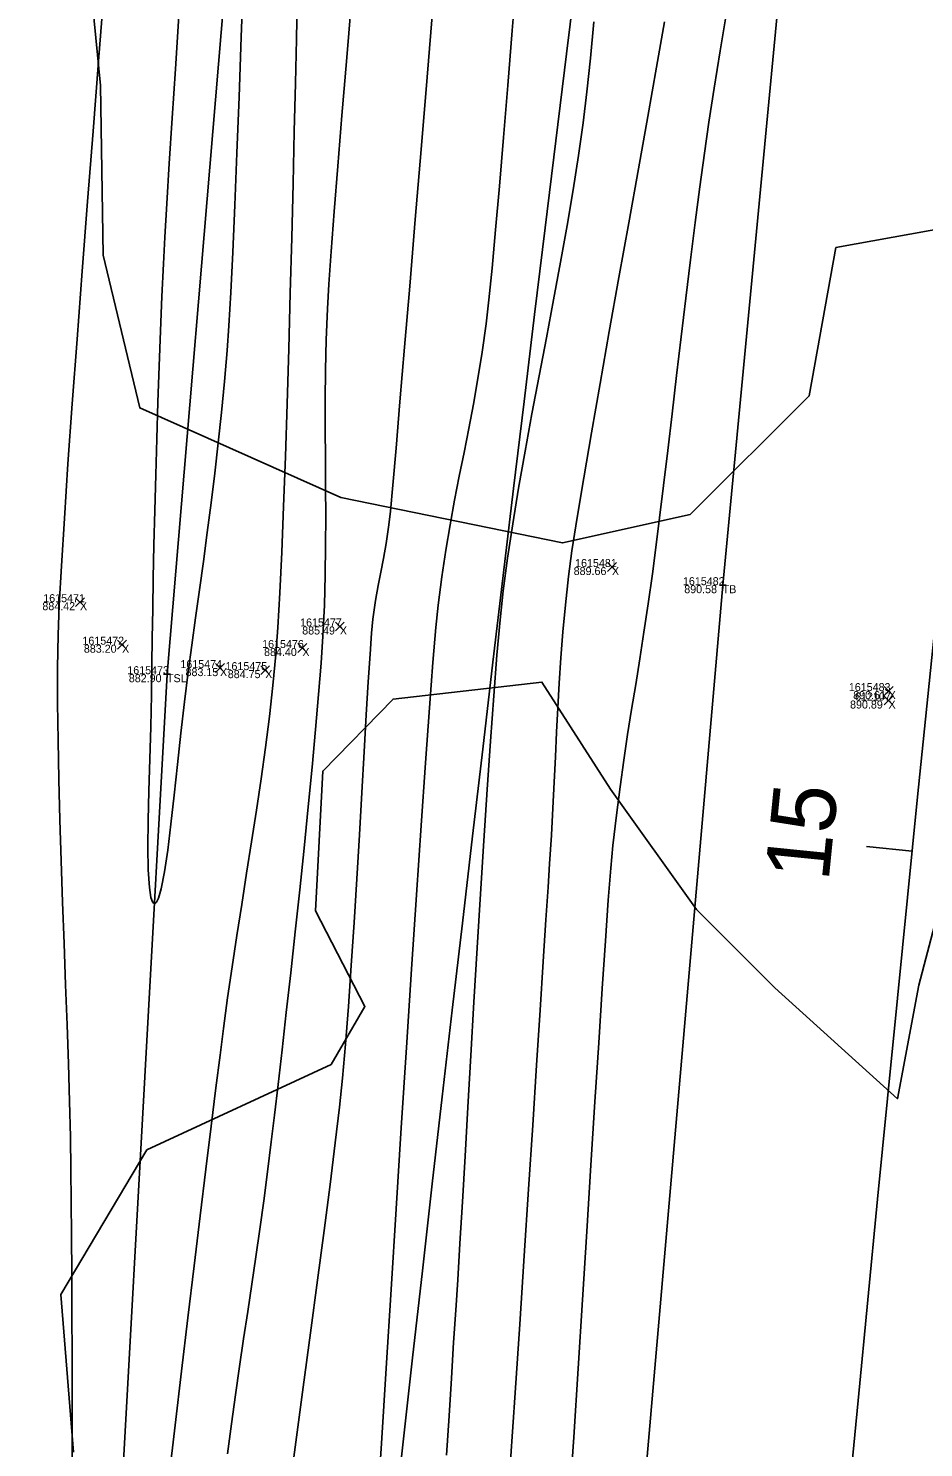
# Model space of a CAD drawing. Extents: x 1957117 to 1971063, y 701601 to 715861.
# Drawn here: x 1962727.3 to 1962766.5, y 703470.4 to 703532.5 of the extents above; entities that cross this region are included whole.
import ezdxf

# ---------------------------------------------------------------- set-up
doc = ezdxf.new("R2010")
doc.units = 0
for name, color, linetype in [('AP_X_Lights', 7, 'Continuous'), ('DT_X_Break_Line', 7, 'Continuous'), ('DT_X_Contour_Major', 7, 'Continuous'), ('DT_X_Contour_Minor', 7, 'Continuous'), ('GE_X_CL_20', 7, 'Continuous'), ('PV_P_Drive', 7, 'Continuous'), ('PV_P_Shoulder', 7, 'Continuous'), ('RS_Raster1', 7, 'Continuous'), ('RW_X_Esmt_RR', 7, 'Continuous'), ('SC_Scratch1', 7, 'Continuous'), ('VG_X_Tree_Line_Rt', 7, 'Continuous')]:
    doc.layers.add(name, color=color, linetype=linetype)

msp = doc.modelspace()

# ---------------------------------------------------------------- linework, layer by layer
at = {"layer": 'AP_X_Lights'}
for p, q in [((1962752.654, 703508.755), (1962753.042, 703509.145)), ((1962752.654, 703509.145), (1962753.042, 703508.755)), ((1962729.394, 703507.219), (1962729.782, 703507.609)), ((1962729.394, 703507.609), (1962729.782, 703507.219)), ((1962740.757, 703506.156), (1962741.145, 703506.546)), ((1962740.757, 703506.546), (1962741.145, 703506.156)), ((1962731.236, 703505.359), (1962731.624, 703505.749)), ((1962731.236, 703505.749), (1962731.624, 703505.359)), ((1962739.119, 703505.214), (1962739.507, 703505.604)), ((1962739.119, 703505.604), (1962739.507, 703505.214)), ((1962735.518, 703504.336), (1962735.906, 703504.726)), ((1962735.518, 703504.726), (1962735.906, 703504.336)), ((1962737.495, 703504.247), (1962737.883, 703504.637)), ((1962737.495, 703504.637), (1962737.883, 703504.247)), ((1962764.747, 703502.918), (1962765.135, 703503.308)), ((1962764.747, 703503.308), (1962765.135, 703502.918)), ((1962764.754, 703503.33), (1962765.142, 703503.72)), ((1962764.754, 703503.72), (1962765.142, 703503.33))]:
    msp.add_line(p, q, dxfattribs=at)
at = {"layer": 'DT_X_Break_Line'}
for points in [[(1962730.818, 703457.798), (1962733.395, 703504.264), (1962741.916, 703605.02), (1962747.624, 703652.087), (1962756.592, 703704.666), (1962761.935, 703754.654), (1962770.271, 703804.276), (1962778.004, 703852.465), (1962787.236, 703902.544), (1962794.92, 703952.201), (1962805.163, 704000.74), (1962815.72, 704050.002), (1962825.218, 704099.5), (1962834.811, 704148.707), (1962846.035, 704198.31), (1962854.549, 704243.654), (1962868.069, 704295.231)], [(1962892.064, 704289.931), (1962881.011, 704234.451), (1962871.969, 704195.37), (1962858.193, 704145.387), (1962849.618, 704095.769), (1962840.196, 704046.83), (1962828.044, 703997.69), (1962822.426, 703949.671), (1962812.618, 703898.591), (1962803.468, 703849.395), (1962793.965, 703803.71), (1962788.733, 703751.727), (1962780.252, 703700.82), (1962774.948, 703651.755), (1962769.57, 703604.236), (1962761.597, 703549.082), (1962757.692, 703508.157), (1962753.044, 703454.513)]]:
    msp.add_lwpolyline(points, dxfattribs=at)
at = {"layer": 'DT_X_Contour_Major'}
for points in [[(1962741.449, 703533.54), (1962741.238, 703531.059), (1962741.04, 703528.692), (1962740.86, 703526.487), (1962740.702, 703524.493), (1962740.571, 703522.755), (1962740.472, 703521.322), (1962740.408, 703520.242), (1962740.354, 703518.887), (1962740.324, 703517.563), (1962740.312, 703516.265), (1962740.312, 703514.985), (1962740.32, 703513.715), (1962740.33, 703512.449), (1962740.336, 703511.179), (1962740.332, 703509.899), (1962740.314, 703508.602), (1962740.275, 703507.279), (1962740.211, 703505.925), (1962740.133, 703504.743), (1962740.025, 703503.374), (1962739.893, 703501.85), (1962739.74, 703500.202), (1962739.571, 703498.461), (1962739.388, 703496.659), (1962739.197, 703494.828), (1962739.001, 703492.999), (1962738.805, 703491.202), (1962738.612, 703489.471), (1962738.426, 703487.835), (1962738.252, 703486.328), (1962738.094, 703484.979), (1962737.955, 703483.82), (1962737.791, 703482.506), (1962737.623, 703481.236), (1962737.451, 703480), (1962737.276, 703478.788), (1962737.1, 703477.592), (1962736.923, 703476.4), (1962736.745, 703475.204), (1962736.567, 703473.993), (1962736.391, 703472.758), (1962736.216, 703471.488), (1962736.043, 703470.174)], [(1962741.449, 703533.54), (1962741.238, 703531.059), (1962741.04, 703528.692), (1962740.86, 703526.487), (1962740.702, 703524.493), (1962740.571, 703522.755), (1962740.472, 703521.322), (1962740.408, 703520.242), (1962740.354, 703518.887), (1962740.324, 703517.563), (1962740.312, 703516.265), (1962740.312, 703514.985), (1962740.32, 703513.715), (1962740.33, 703512.449), (1962740.336, 703511.179), (1962740.332, 703509.899), (1962740.314, 703508.602), (1962740.275, 703507.279), (1962740.211, 703505.925), (1962740.133, 703504.743), (1962740.025, 703503.374), (1962739.893, 703501.85), (1962739.74, 703500.202), (1962739.571, 703498.461), (1962739.388, 703496.659), (1962739.197, 703494.828), (1962739.001, 703492.999), (1962738.805, 703491.202), (1962738.612, 703489.471), (1962738.426, 703487.835), (1962738.252, 703486.328), (1962738.094, 703484.979), (1962737.955, 703483.82), (1962737.791, 703482.506), (1962737.623, 703481.236), (1962737.451, 703480), (1962737.276, 703478.788), (1962737.1, 703477.592), (1962736.923, 703476.4), (1962736.745, 703475.204), (1962736.567, 703473.993), (1962736.391, 703472.758), (1962736.216, 703471.488), (1962736.043, 703470.174)], [(1962757.877, 703533.28), (1962757.583, 703531.531), (1962757.318, 703529.891), (1962757.09, 703528.406), (1962756.896, 703527.055), (1962756.698, 703525.584), (1962756.495, 703524.02), (1962756.29, 703522.387), (1962756.084, 703520.709), (1962755.88, 703519.012), (1962755.678, 703517.32), (1962755.481, 703515.657), (1962755.289, 703514.05), (1962755.106, 703512.521), (1962754.932, 703511.097), (1962754.769, 703509.802), (1962754.62, 703508.66), (1962754.434, 703507.339), (1962754.25, 703506.107), (1962754.067, 703504.942), (1962753.887, 703503.821), (1962753.71, 703502.723), (1962753.536, 703501.624), (1962753.367, 703500.502), (1962753.203, 703499.335), (1962753.044, 703498.101), (1962752.892, 703496.776), (1962752.8, 703495.787), (1962752.69, 703494.382), (1962752.564, 703492.608), (1962752.424, 703490.515), (1962752.271, 703488.148), (1962752.107, 703485.557), (1962751.933, 703482.788), (1962751.752, 703479.891), (1962751.564, 703476.911), (1962751.372, 703473.899), (1962751.178, 703470.9), (1962750.982, 703467.964)], [(1962757.877, 703533.28), (1962757.583, 703531.531), (1962757.318, 703529.891), (1962757.09, 703528.406), (1962756.896, 703527.055), (1962756.698, 703525.584), (1962756.495, 703524.02), (1962756.29, 703522.387), (1962756.084, 703520.709), (1962755.88, 703519.012), (1962755.678, 703517.32), (1962755.481, 703515.657), (1962755.289, 703514.05), (1962755.106, 703512.521), (1962754.932, 703511.097), (1962754.769, 703509.802), (1962754.62, 703508.66), (1962754.434, 703507.339), (1962754.25, 703506.107), (1962754.067, 703504.942), (1962753.887, 703503.821), (1962753.71, 703502.723), (1962753.536, 703501.624), (1962753.367, 703500.502), (1962753.203, 703499.335), (1962753.044, 703498.101), (1962752.892, 703496.776), (1962752.8, 703495.787), (1962752.69, 703494.382), (1962752.564, 703492.608), (1962752.424, 703490.515), (1962752.271, 703488.148), (1962752.107, 703485.557), (1962751.933, 703482.788), (1962751.752, 703479.891), (1962751.564, 703476.911), (1962751.372, 703473.899), (1962751.178, 703470.9), (1962750.982, 703467.964)]]:
    msp.add_lwpolyline(points, dxfattribs=at)
at = {"layer": 'DT_X_Contour_Minor'}
for points in [[(1962736.74, 703534.821), (1962736.641, 703532.124), (1962736.544, 703529.52), (1962736.449, 703527.054), (1962736.358, 703524.773), (1962736.27, 703522.723), (1962736.185, 703520.95), (1962736.105, 703519.5), (1962736.03, 703518.418), (1962735.911, 703517.061), (1962735.778, 703515.713), (1962735.633, 703514.378), (1962735.48, 703513.057), (1962735.319, 703511.753), (1962735.153, 703510.466), (1962734.984, 703509.199), (1962734.815, 703507.955), (1962734.648, 703506.734), (1962734.484, 703505.539), (1962734.325, 703504.371), (1962734.16, 703503.059), (1962734.004, 703501.691), (1962733.854, 703500.313), (1962733.709, 703498.97), (1962733.567, 703497.709), (1962733.427, 703496.576), (1962733.285, 703495.617), (1962733.142, 703494.877), (1962733.024, 703494.476), (1962732.933, 703494.3), (1962732.871, 703494.249), (1962732.839, 703494.244), (1962732.809, 703494.253), (1962732.754, 703494.314), (1962732.687, 703494.505), (1962732.623, 703494.931), (1962732.578, 703495.703), (1962732.564, 703496.697), (1962732.576, 703497.867), (1962732.604, 703499.165), (1962732.642, 703500.544), (1962732.682, 703501.957), (1962732.717, 703503.356), (1962732.738, 703504.695), (1962732.751, 703505.839), (1962732.77, 703507.103), (1962732.795, 703508.467), (1962732.825, 703509.914), (1962732.861, 703511.425), (1962732.902, 703512.981), (1962732.947, 703514.564), (1962732.997, 703516.154), (1962733.052, 703517.733), (1962733.111, 703519.282), (1962733.174, 703520.783), (1962733.24, 703522.216), (1962733.302, 703523.373), (1962733.387, 703524.846), (1962733.495, 703526.595), (1962733.62, 703528.575), (1962733.762, 703530.743), (1962733.915, 703533.057)], [(1962736.74, 703534.821), (1962736.641, 703532.124), (1962736.544, 703529.52), (1962736.449, 703527.054), (1962736.358, 703524.773), (1962736.27, 703522.723), (1962736.185, 703520.95), (1962736.105, 703519.5), (1962736.03, 703518.418), (1962735.911, 703517.061), (1962735.778, 703515.713), (1962735.633, 703514.378), (1962735.48, 703513.057), (1962735.319, 703511.753), (1962735.153, 703510.466), (1962734.984, 703509.199), (1962734.815, 703507.955), (1962734.648, 703506.734), (1962734.484, 703505.539), (1962734.325, 703504.371), (1962734.16, 703503.059), (1962734.004, 703501.691), (1962733.854, 703500.313), (1962733.709, 703498.97), (1962733.567, 703497.709), (1962733.427, 703496.576), (1962733.285, 703495.617), (1962733.142, 703494.877), (1962733.024, 703494.476), (1962732.933, 703494.3), (1962732.871, 703494.249), (1962732.839, 703494.244), (1962732.809, 703494.253), (1962732.754, 703494.314), (1962732.687, 703494.505), (1962732.623, 703494.931), (1962732.578, 703495.703), (1962732.564, 703496.697), (1962732.576, 703497.867), (1962732.604, 703499.165), (1962732.642, 703500.544), (1962732.682, 703501.957), (1962732.717, 703503.356), (1962732.738, 703504.695), (1962732.751, 703505.839), (1962732.77, 703507.103), (1962732.795, 703508.467), (1962732.825, 703509.914), (1962732.861, 703511.425), (1962732.902, 703512.981), (1962732.947, 703514.564), (1962732.997, 703516.154), (1962733.052, 703517.733), (1962733.111, 703519.282), (1962733.174, 703520.783), (1962733.24, 703522.216), (1962733.302, 703523.373), (1962733.387, 703524.846), (1962733.495, 703526.595), (1962733.62, 703528.575), (1962733.762, 703530.743), (1962733.915, 703533.057)], [(1962748.692, 703534.882), (1962748.493, 703532.409), (1962748.299, 703530.011), (1962748.111, 703527.732), (1962747.931, 703525.613), (1962747.763, 703523.696), (1962747.607, 703522.025), (1962747.468, 703520.641), (1962747.346, 703519.587), (1962747.175, 703518.354), (1962746.99, 703517.19), (1962746.794, 703516.08), (1962746.591, 703515.008), (1962746.384, 703513.96), (1962746.176, 703512.919), (1962745.971, 703511.87), (1962745.772, 703510.798), (1962745.583, 703509.688), (1962745.406, 703508.523), (1962745.247, 703507.289), (1962745.148, 703506.302), (1962745.022, 703504.782), (1962744.871, 703502.791), (1962744.698, 703500.392), (1962744.507, 703497.645), (1962744.303, 703494.614), (1962744.087, 703491.36), (1962743.865, 703487.945), (1962743.638, 703484.431), (1962743.412, 703480.88), (1962743.189, 703477.353), (1962742.973, 703473.913), (1962742.767, 703470.621), (1962742.576, 703467.54)], [(1962748.692, 703534.882), (1962748.493, 703532.409), (1962748.299, 703530.011), (1962748.111, 703527.732), (1962747.931, 703525.613), (1962747.763, 703523.696), (1962747.607, 703522.025), (1962747.468, 703520.641), (1962747.346, 703519.587), (1962747.175, 703518.354), (1962746.99, 703517.19), (1962746.794, 703516.08), (1962746.591, 703515.008), (1962746.384, 703513.96), (1962746.176, 703512.919), (1962745.971, 703511.87), (1962745.772, 703510.798), (1962745.583, 703509.688), (1962745.406, 703508.523), (1962745.247, 703507.289), (1962745.148, 703506.302), (1962745.022, 703504.782), (1962744.871, 703502.791), (1962744.698, 703500.392), (1962744.507, 703497.645), (1962744.303, 703494.614), (1962744.087, 703491.36), (1962743.865, 703487.945), (1962743.638, 703484.431), (1962743.412, 703480.88), (1962743.189, 703477.353), (1962742.973, 703473.913), (1962742.767, 703470.621), (1962742.576, 703467.54)], [(1962729.245, 703468.762), (1962729.247, 703470.683), (1962729.247, 703472.596), (1962729.243, 703474.478), (1962729.237, 703476.306), (1962729.229, 703478.055), (1962729.219, 703479.702), (1962729.208, 703481.223), (1962729.195, 703482.595), (1962729.172, 703484.036), (1962729.135, 703485.584), (1962729.085, 703487.22), (1962729.027, 703488.926), (1962728.963, 703490.686), (1962728.897, 703492.482), (1962728.831, 703494.295), (1962728.768, 703496.107), (1962728.712, 703497.902), (1962728.666, 703499.661), (1962728.632, 703501.367), (1962728.614, 703503.002), (1962728.614, 703504.548), (1962728.636, 703505.987), (1962728.686, 703507.287), (1962728.778, 703509.002), (1962728.906, 703511.078), (1962729.066, 703513.459), (1962729.253, 703516.09), (1962729.461, 703518.917), (1962729.685, 703521.883), (1962729.921, 703524.935), (1962730.162, 703528.016), (1962730.403, 703531.072), (1962730.64, 703534.047)], [(1962729.245, 703468.762), (1962729.247, 703470.683), (1962729.247, 703472.596), (1962729.243, 703474.478), (1962729.237, 703476.306), (1962729.229, 703478.055), (1962729.219, 703479.702), (1962729.208, 703481.223), (1962729.195, 703482.595), (1962729.172, 703484.036), (1962729.135, 703485.584), (1962729.085, 703487.22), (1962729.027, 703488.926), (1962728.963, 703490.686), (1962728.897, 703492.482), (1962728.831, 703494.295), (1962728.768, 703496.107), (1962728.712, 703497.902), (1962728.666, 703499.661), (1962728.632, 703501.367), (1962728.614, 703503.002), (1962728.614, 703504.548), (1962728.636, 703505.987), (1962728.686, 703507.287), (1962728.778, 703509.002), (1962728.906, 703511.078), (1962729.066, 703513.459), (1962729.253, 703516.09), (1962729.461, 703518.917), (1962729.685, 703521.883), (1962729.921, 703524.935), (1962730.162, 703528.016), (1962730.403, 703531.072), (1962730.64, 703534.047)], [(1962739.088, 703533.717), (1962739.051, 703532.035), (1962739.008, 703530.111), (1962738.959, 703527.99), (1962738.905, 703525.721), (1962738.846, 703523.35), (1962738.783, 703520.923), (1962738.715, 703518.488), (1962738.643, 703516.09), (1962738.569, 703513.778), (1962738.491, 703511.597), (1962738.41, 703509.595), (1962738.327, 703507.818), (1962738.243, 703506.313), (1962738.157, 703505.127), (1962738.028, 703503.775), (1962737.874, 703502.416), (1962737.7, 703501.052), (1962737.51, 703499.683), (1962737.307, 703498.312), (1962737.095, 703496.94), (1962736.878, 703495.568), (1962736.661, 703494.198), (1962736.447, 703492.832), (1962736.24, 703491.47), (1962736.045, 703490.114), (1962735.864, 703488.766), (1962735.717, 703487.608), (1962735.536, 703486.174), (1962735.327, 703484.501), (1962735.095, 703482.623), (1962734.843, 703480.577), (1962734.578, 703478.399), (1962734.303, 703476.125), (1962734.024, 703473.789), (1962733.746, 703471.43), (1962733.473, 703469.081)], [(1962739.088, 703533.717), (1962739.051, 703532.035), (1962739.008, 703530.111), (1962738.959, 703527.99), (1962738.905, 703525.721), (1962738.846, 703523.35), (1962738.783, 703520.923), (1962738.715, 703518.488), (1962738.643, 703516.09), (1962738.569, 703513.778), (1962738.491, 703511.597), (1962738.41, 703509.595), (1962738.327, 703507.818), (1962738.243, 703506.313), (1962738.157, 703505.127), (1962738.028, 703503.775), (1962737.874, 703502.416), (1962737.7, 703501.052), (1962737.51, 703499.683), (1962737.307, 703498.312), (1962737.095, 703496.94), (1962736.878, 703495.568), (1962736.661, 703494.198), (1962736.447, 703492.832), (1962736.24, 703491.47), (1962736.045, 703490.114), (1962735.864, 703488.766), (1962735.717, 703487.608), (1962735.536, 703486.174), (1962735.327, 703484.501), (1962735.095, 703482.623), (1962734.843, 703480.577), (1962734.578, 703478.399), (1962734.303, 703476.125), (1962734.024, 703473.789), (1962733.746, 703471.43), (1962733.473, 703469.081)], [(1962745.039, 703533.592), (1962744.772, 703530.38), (1962744.507, 703527.209), (1962744.252, 703524.142), (1962744.009, 703521.24), (1962743.784, 703518.565), (1962743.582, 703516.182), (1962743.408, 703514.15), (1962743.266, 703512.535), (1962743.162, 703511.396), (1962743.1, 703510.798), (1962742.981, 703509.98), (1962742.86, 703509.317), (1962742.74, 703508.733), (1962742.622, 703508.148), (1962742.506, 703507.485), (1962742.394, 703506.666), (1962742.338, 703506.063), (1962742.271, 703505.135), (1962742.195, 703503.929), (1962742.109, 703502.49), (1962742.015, 703500.864), (1962741.913, 703499.096), (1962741.805, 703497.233), (1962741.692, 703495.319), (1962741.573, 703493.402), (1962741.451, 703491.526), (1962741.325, 703489.737), (1962741.198, 703488.08), (1962741.069, 703486.603), (1962740.936, 703485.328), (1962740.753, 703483.764), (1962740.527, 703481.953), (1962740.266, 703479.937), (1962739.978, 703477.759), (1962739.671, 703475.461), (1962739.352, 703473.087), (1962739.029, 703470.678), (1962738.709, 703468.276)], [(1962745.039, 703533.592), (1962744.772, 703530.38), (1962744.507, 703527.209), (1962744.252, 703524.142), (1962744.009, 703521.24), (1962743.784, 703518.565), (1962743.582, 703516.182), (1962743.408, 703514.15), (1962743.266, 703512.535), (1962743.162, 703511.396), (1962743.1, 703510.798), (1962742.981, 703509.98), (1962742.86, 703509.317), (1962742.74, 703508.733), (1962742.622, 703508.148), (1962742.506, 703507.485), (1962742.394, 703506.666), (1962742.338, 703506.063), (1962742.271, 703505.135), (1962742.195, 703503.929), (1962742.109, 703502.49), (1962742.015, 703500.864), (1962741.913, 703499.096), (1962741.805, 703497.233), (1962741.692, 703495.319), (1962741.573, 703493.402), (1962741.451, 703491.526), (1962741.325, 703489.737), (1962741.198, 703488.08), (1962741.069, 703486.603), (1962740.936, 703485.328), (1962740.753, 703483.764), (1962740.527, 703481.953), (1962740.266, 703479.937), (1962739.978, 703477.759), (1962739.671, 703475.461), (1962739.352, 703473.087), (1962739.029, 703470.678), (1962738.709, 703468.276)], [(1962752.062, 703532.787), (1962751.911, 703531.209), (1962751.754, 703529.732), (1962751.592, 703528.376), (1962751.394, 703526.946), (1962751.158, 703525.444), (1962750.892, 703523.883), (1962750.603, 703522.277), (1962750.298, 703520.638), (1962749.983, 703518.979), (1962749.665, 703517.313), (1962749.353, 703515.654), (1962749.051, 703514.014), (1962748.768, 703512.407), (1962748.51, 703510.846), (1962748.285, 703509.343), (1962748.099, 703507.913), (1962747.963, 703506.636), (1962747.823, 703505.09), (1962747.68, 703503.313), (1962747.535, 703501.343), (1962747.389, 703499.218), (1962747.243, 703496.976), (1962747.098, 703494.655), (1962746.955, 703492.292), (1962746.816, 703489.926), (1962746.681, 703487.594), (1962746.551, 703485.335), (1962746.428, 703483.187), (1962746.312, 703481.187), (1962746.205, 703479.373), (1962746.107, 703477.784), (1962746.021, 703476.457), (1962745.926, 703475.034), (1962745.827, 703473.487), (1962745.725, 703471.84), (1962745.619, 703470.117)], [(1962752.062, 703532.787), (1962751.911, 703531.209), (1962751.754, 703529.732), (1962751.592, 703528.376), (1962751.394, 703526.946), (1962751.158, 703525.444), (1962750.892, 703523.883), (1962750.603, 703522.277), (1962750.298, 703520.638), (1962749.983, 703518.979), (1962749.665, 703517.313), (1962749.353, 703515.654), (1962749.051, 703514.014), (1962748.768, 703512.407), (1962748.51, 703510.846), (1962748.285, 703509.343), (1962748.099, 703507.913), (1962747.963, 703506.636), (1962747.823, 703505.09), (1962747.68, 703503.313), (1962747.535, 703501.343), (1962747.389, 703499.218), (1962747.243, 703496.976), (1962747.098, 703494.655), (1962746.955, 703492.292), (1962746.816, 703489.926), (1962746.681, 703487.594), (1962746.551, 703485.335), (1962746.428, 703483.187), (1962746.312, 703481.187), (1962746.205, 703479.373), (1962746.107, 703477.784), (1962746.021, 703476.457), (1962745.926, 703475.034), (1962745.827, 703473.487), (1962745.725, 703471.84), (1962745.619, 703470.117)], [(1962755.148, 703532.789), (1962754.804, 703530.806), (1962754.422, 703528.646), (1962754.012, 703526.359), (1962753.587, 703523.998), (1962753.157, 703521.612), (1962752.734, 703519.254), (1962752.328, 703516.974), (1962751.951, 703514.823), (1962751.613, 703512.853), (1962751.327, 703511.114), (1962751.102, 703509.658), (1962750.951, 703508.536), (1962750.814, 703507.292), (1962750.703, 703506.11), (1962750.612, 703504.977), (1962750.539, 703503.879), (1962750.477, 703502.8), (1962750.424, 703501.728), (1962750.374, 703500.649), (1962750.323, 703499.547), (1962750.267, 703498.41), (1962750.201, 703497.223), (1962750.121, 703495.972), (1962750.054, 703494.957), (1962749.961, 703493.519), (1962749.845, 703491.708), (1962749.709, 703489.576), (1962749.555, 703487.171), (1962749.387, 703484.546), (1962749.206, 703481.749), (1962749.015, 703478.833), (1962748.818, 703475.847), (1962748.615, 703472.842), (1962748.411, 703469.868)], [(1962755.148, 703532.789), (1962754.804, 703530.806), (1962754.422, 703528.646), (1962754.012, 703526.359), (1962753.587, 703523.998), (1962753.157, 703521.612), (1962752.734, 703519.254), (1962752.328, 703516.974), (1962751.951, 703514.823), (1962751.613, 703512.853), (1962751.327, 703511.114), (1962751.102, 703509.658), (1962750.951, 703508.536), (1962750.814, 703507.292), (1962750.703, 703506.11), (1962750.612, 703504.977), (1962750.539, 703503.879), (1962750.477, 703502.8), (1962750.424, 703501.728), (1962750.374, 703500.649), (1962750.323, 703499.547), (1962750.267, 703498.41), (1962750.201, 703497.223), (1962750.121, 703495.972), (1962750.054, 703494.957), (1962749.961, 703493.519), (1962749.845, 703491.708), (1962749.709, 703489.576), (1962749.555, 703487.171), (1962749.387, 703484.546), (1962749.206, 703481.749), (1962749.015, 703478.833), (1962748.818, 703475.847), (1962748.615, 703472.842), (1962748.411, 703469.868)]]:
    msp.add_lwpolyline(points, dxfattribs=at)
at = {"layer": 'GE_X_CL_20'}
msp.add_line((1962765.974, 703496.53), (1962763.984, 703496.73), dxfattribs=at)
msp.add_arc((1968466.781, 702923.066), 5729.578, 166.495347, 177.813939, dxfattribs=at)
at = {"layer": 'PV_P_Drive'}
for p, q in [((1962757.692, 703508.303), (1962757.692, 703508.011)), ((1962757.546, 703508.157), (1962757.838, 703508.157)), ((1962757.692, 703508.157), (1962757.692, 703508.157)), ((1962733.249, 703504.264), (1962733.541, 703504.264)), ((1962733.395, 703504.41), (1962733.395, 703504.118)), ((1962733.395, 703504.264), (1962733.395, 703504.264))]:
    msp.add_line(p, q, dxfattribs=at)
at = {"layer": 'RW_X_Esmt_RR'}
msp.add_arc((1968454.457, 702829.895), 5746.578, 171.9960402, 176.8809291, dxfattribs=at)
at = {"layer": 'VG_X_Tree_Line_Rt'}
for points in [[(1962768.423, 703551.431), (1962764.905, 703547.369), (1962758.265, 703542.919), (1962754.521, 703542.028), (1962748.665, 703545.881), (1962742.849, 703546.119), (1962733.475, 703545.46), (1962729.526, 703539.848), (1962730.485, 703530.009), (1962730.61, 703522.594), (1962732.202, 703515.91), (1962740.996, 703511.985), (1962750.686, 703510.002), (1962756.264, 703511.25), (1962761.476, 703516.434), (1962762.64, 703522.922), (1962769.998, 703524.249)], [(1962767.853, 703496.716), (1962766.27, 703490.671), (1962765.341, 703485.696), (1962759.976, 703490.544), (1962756.542, 703493.978), (1962752.788, 703499.239), (1962749.79, 703503.923), (1962743.283, 703503.18), (1962740.205, 703500.028), (1962739.886, 703493.911), (1962742.051, 703489.733), (1962740.567, 703487.19), (1962732.514, 703483.461), (1962728.751, 703477.132), (1962729.305, 703470.239)]]:
    msp.add_lwpolyline(points, dxfattribs=at)

# ---------------------------------------------------------------- texts
at = {"layer": 'GE_X_CL_20'}
msp.add_text('15', height=2.8, rotation=84.25574, dxfattribs=at).set_placement((1962762.319, 703495.167))
at = {"layer": 'PV_P_Shoulder'}
for s, p in [('889.66', (1962751.175, 703508.6)), ('890.58', (1962756.011, 703507.807)), ('884.42', (1962727.946, 703507.064)), ('885.49', (1962739.306, 703506.001)), ('883.20', (1962729.76, 703505.204)), ('884.40', (1962737.638, 703505.059)), ('883.15', (1962734.205, 703504.181)), ('882.90', (1962731.725, 703503.914)), ('884.75', (1962736.052, 703504.092)), ('890.61', (1962763.396, 703503.175)), ('890.89', (1962763.26, 703502.763))]:
    msp.add_text(s, height=0.35, dxfattribs=at).set_placement(p)
at = {"layer": 'RS_Raster1'}
for s, p in [('1615481', (1962751.238, 703508.95)), ('1615482', (1962755.953, 703508.157)), ('1615471', (1962727.984, 703507.414)), ('1615477', (1962739.215, 703506.351)), ('1615472', (1962729.697, 703505.554)), ('1615476', (1962737.555, 703505.409)), ('1615473', (1962731.659, 703504.264)), ('1615474', (1962733.979, 703504.531)), ('1615475', (1962735.953, 703504.442)), ('1615483', (1962763.207, 703503.525)), ('612107', (1962763.478, 703503.113))]:
    msp.add_text(s, height=0.35, dxfattribs=at).set_placement(p)
at = {"layer": 'SC_Scratch1'}
for s, p in [('X', (1962752.848, 703508.6)), ('TB', (1962757.692, 703507.807)), ('X', (1962729.588, 703507.064)), ('X', (1962740.951, 703506.001)), ('X', (1962731.43, 703505.204)), ('X', (1962739.313, 703505.059)), ('X', (1962735.712, 703504.181)), ('TSL', (1962733.395, 703503.914)), ('X', (1962737.689, 703504.092)), ('X', (1962764.948, 703503.175)), ('X', (1962764.941, 703502.763))]:
    msp.add_text(s, height=0.35, dxfattribs=at).set_placement(p)

doc.saveas('drawing.dxf')
